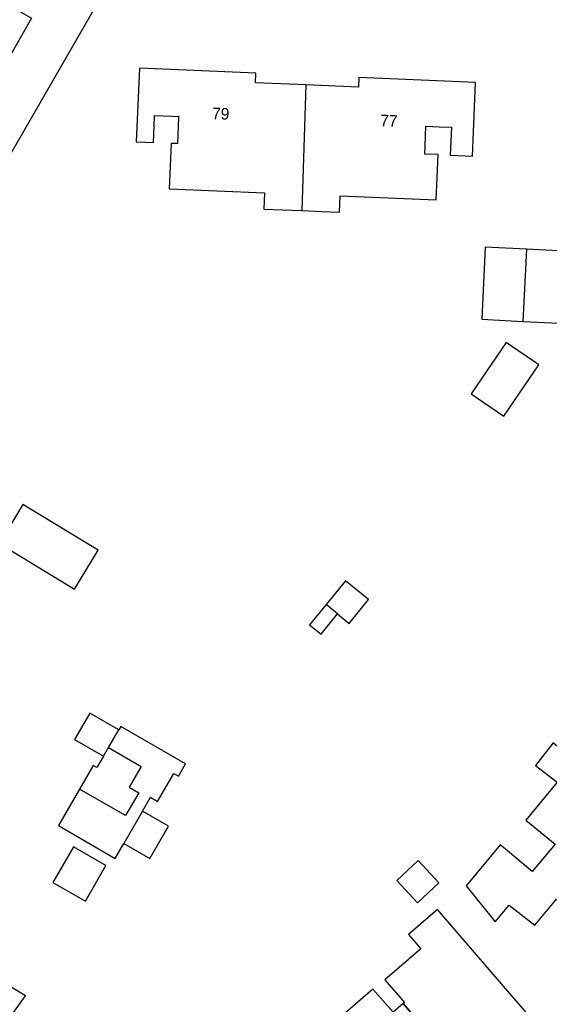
# Model space of a CAD drawing. Extents: x 161772 to 163123, y 383092 to 383917.
# Drawn here: x 162435.2 to 162480.9, y 383557.9 to 383642.9 of the extents above; entities that cross this region are included whole.
import ezdxf

# ---------------------------------------------------------------- set-up
doc = ezdxf.new("R2010")
doc.units = 0
for name, color, linetype in [('IMGEO_Pand', 7, 'Continuous'), ('IMGEO_Pand_nummerreeks', 7, 'Continuous'), ('IMGEO_Pand_overbouw', 7, 'Continuous'), ('IMGEO_Voetpad_open', 7, 'Continuous')]:
    doc.layers.add(name, color=color, linetype=linetype)

msp = doc.modelspace()

# ---------------------------------------------------------------- linework, layer by layer
at = {"layer": 'IMGEO_Pand'}
for points in [[(162459.863, 383637.267), (162455.508, 383637.45), (162455.544, 383638.286), (162445.494, 383638.709), (162445.228, 383632.355), (162446.707, 383632.293), (162446.8, 383634.523), (162446.805, 383634.642), (162448.329, 383634.578), (162448.89, 383634.554), (162448.877, 383634.436), (162448.784, 383632.207), (162448.231, 383632.23), (162448.068, 383628.314), (162456.306, 383627.97), (162456.248, 383626.562), (162459.509, 383626.426)], [(162459.509, 383626.426), (162461.244, 383626.353), (162462.763, 383626.29), (162462.822, 383627.689), (162471.115, 383627.342), (162471.279, 383631.259), (162470.129, 383631.306), (162470.158, 383632.003), (162470.229, 383633.706), (162471.378, 383633.658), (162472.44, 383633.614), (162472.34, 383631.215), (162474.259, 383631.135), (162474.316, 383632.497), (162474.527, 383637.492), (162464.438, 383637.917), (162464.402, 383637.076), (162459.863, 383637.267)], [(162459.863, 383637.267), (162459.509, 383626.426)], [(162478.916, 383623.087), (162475.36, 383623.269), (162475.047, 383617.049), (162478.603, 383616.867)], [(162478.603, 383616.867), (162482.982, 383616.643), (162483.295, 383622.863), (162478.916, 383623.087)], [(162478.916, 383623.087), (162478.603, 383616.867)], [(162474.126, 383610.606), (162476.957, 383608.671), (162479.984, 383613.1), (162477.152, 383615.034), (162474.126, 383610.606)], [(162439.904, 383593.748), (162441.938, 383597.106), (162435.424, 383601.051), (162433.39, 383597.693), (162439.904, 383593.748)], [(162462.611, 383591.616), (162463.614, 383590.799), (162465.284, 383592.852), (162463.288, 383594.476), (162461.618, 383592.423)], [(162461.618, 383592.423), (162460.192, 383590.671), (162461.185, 383589.863), (162462.611, 383591.616)], [(162462.611, 383591.616), (162461.618, 383592.423)], [(162491.689, 383568.92), (162491.827, 383569.086), (162491.399, 383569.44), (162493.8, 383572.337), (162494.053, 383572.128), (162495.473, 383573.841), (162495.15, 383574.109), (162496.014, 383575.152), (162492.165, 383578.343), (162488.671, 383581.24), (162486.746, 383582.836), (162485.376, 383583.002), (162484.991, 383583.321), (162482.14, 383579.711), (162481.216, 383580.476), (162479.686, 383578.547), (162481.566, 383577.087)], [(162443.709, 383581.612), (162441.203, 383583.056), (162439.893, 383580.783), (162442.396, 383579.34)], [(162442.821, 383580.077), (162443.709, 383581.612)], [(162445.751, 383574.585), (162446.448, 383575.792), (162447.065, 383575.436), (162448.46, 383577.85), (162448.858, 383577.62), (162449.471, 383578.68), (162443.882, 383581.912), (162443.709, 383581.612)], [(162442.821, 383580.077), (162445.638, 383578.449), (162444.598, 383576.65), (162445.432, 383576.168), (162444.302, 383574.21), (162440.328, 383576.504)], [(162442.396, 383579.34), (162442.821, 383580.077)], [(162442.396, 383579.34), (162441.824, 383578.348), (162441.501, 383578.535), (162440.328, 383576.504)], [(162440.328, 383576.504), (162438.504, 383573.345), (162443.405, 383570.518), (162444.145, 383571.8)], [(162481.566, 383577.087), (162478.866, 383573.829), (162481.383, 383571.745), (162479.42, 383569.376), (162477.097, 383571.301), (162476.648, 383571.673), (162473.721, 383568.14), (162476.216, 383565.042), (162477.407, 383566.479), (162479.628, 383564.76), (162481.496, 383567.012), (162486.735, 383562.944), (162491.689, 383568.92)], [(162445.751, 383574.585), (162444.145, 383571.8)], [(162444.145, 383571.8), (162446.389, 383570.505), (162447.996, 383573.29), (162445.751, 383574.585)], [(162438.032, 383568.441), (162440.839, 383566.823), (162442.609, 383569.891), (162439.802, 383571.51), (162438.032, 383568.441)], [(162469.503, 383566.689), (162471.355, 383568.41), (162469.56, 383570.341), (162467.708, 383568.621), (162469.503, 383566.689)], [(162474.109, 383551.216), (162474.473, 383550.793), (162474.95, 383551.203), (162475.284, 383550.816), (162477.742, 383552.933), (162477.425, 383553.302), (162480.209, 383555.701), (162476.945, 383559.49), (162471.245, 383566.107), (162468.723, 383563.934), (162469.785, 383562.701), (162466.692, 383560.036), (162468.378, 383558.079), (162468.275, 383557.989), (162471.21, 383554.582), (162474.109, 383551.216)], [(162433.118, 383555.18), (162435.667, 383558.655), (162429.844, 383562.175), (162427.624, 383558.501)], [(162467.652, 383545.655), (162469.915, 383547.604), (162470.269, 383547.191), (162472.538, 383549.153), (162472.187, 383549.562), (162473.282, 383550.505), (162470.019, 383554.293), (162467.411, 383557.245), (162465.645, 383559.222), (162460.093, 383554.438)]]:
    msp.add_lwpolyline(points, dxfattribs=at)
at = {"layer": 'IMGEO_Pand_overbouw'}
msp.add_lwpolyline([(162467.411, 383557.245), (162470.019, 383554.293), (162473.282, 383550.505), (162474.109, 383551.216), (162471.21, 383554.582), (162468.275, 383557.989)], close=True, dxfattribs=at)
at = {"layer": 'IMGEO_Voetpad_open'}
for points in [[(162375.184, 383528.714), (162442.25, 383644.984)], [(162434.773, 383643.833), (162436.167, 383643.033), (162433.258, 383637.965)]]:
    msp.add_lwpolyline(points, dxfattribs=at)

# ---------------------------------------------------------------- texts
at = {"layer": 'IMGEO_Pand_nummerreeks'}
for s, p in [('79', (162451.753, 383634.325)), ('77', (162466.27, 383633.714))]:
    msp.add_text(s, height=1, rotation=357.59358, dxfattribs=at).set_placement(p)

doc.saveas('drawing.dxf')
